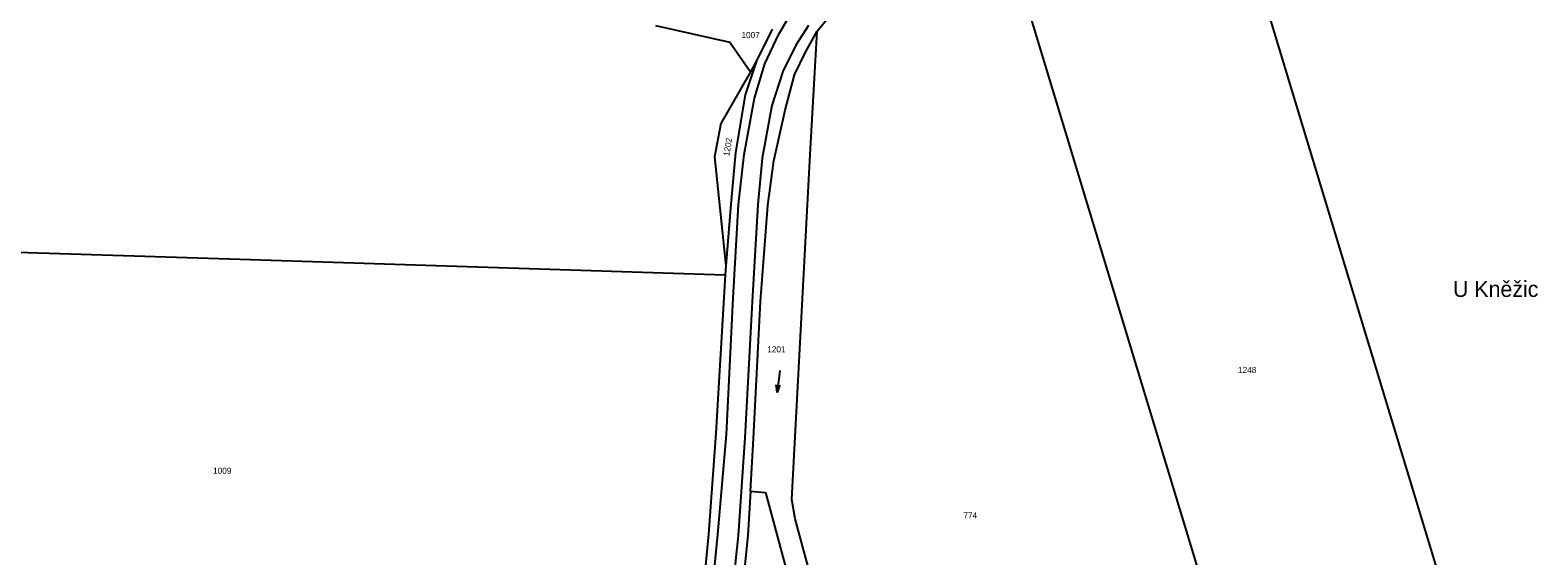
# Model space of a CAD drawing. Extents: x -812394 to -807601, y -1013097 to -1009266.
# Drawn here: x -811185.3 to -810769.5, y -1011122.9 to -1010977.8 of the extents above; entities that cross this region are included whole.
import ezdxf

# ---------------------------------------------------------------- set-up
doc = ezdxf.new("R2010")
doc.units = 0
for name, color, linetype in [('Default', 7, 'Continuous'), ('KN_HRANICE', 7, 'Continuous'), ('KN_KULTURY', 7, 'Continuous'), ('KN_PARCELY', 7, 'Continuous'), ('KN_SLUCKY', 7, 'Continuous')]:
    doc.layers.add(name, color=color, linetype=linetype)

# ---------------------------------------------------------------- blocks, each defined once
blk = doc.blocks.new('802')
at = {"layer": 'Default'}
blk.add_line((-3, 0), (3, 0), dxfattribs=at)
blk.add_lwpolyline([(1, 0.5), (3, 0), (1, -0.5)], dxfattribs=at)

msp = doc.modelspace()

# ---------------------------------------------------------------- linework, layer by layer
at = {"layer": 'KN_HRANICE'}
for p, q in [((-810854.65, -1010937.39), (-810817.55, -1011059.91)), ((-810877.77, -1011078.41), (-810915.45, -1010954)), ((-810968.23, -1010978.09), (-810963.27, -1010971.99)), ((-811012.84, -1010976.5), (-810992.33, -1010981.12)), ((-810980.68, -1010977.48), (-810984.94, -1010986.25)), ((-810971.47, -1010983.86), (-810968.23, -1010978.09)), ((-810970.21, -1011012.14), (-810968.23, -1010978.09)), ((-810992.33, -1010981.12), (-810986.67, -1010989.28)), ((-810984.94, -1010986.25), (-810988.06, -1010995.64)), ((-810984.94, -1010986.25), (-810986.67, -1010989.28)), ((-810974.52, -1010990.17), (-810971.47, -1010983.86)), ((-810986.67, -1010989.28), (-810994.78, -1011003.54)), ((-810977.06, -1010999.91), (-810974.52, -1010990.17)), ((-810988.06, -1010995.64), (-810990.73, -1011011.55)), ((-810980.21, -1011013.87), (-810977.06, -1010999.91)), ((-810994.78, -1011003.54), (-810996.57, -1011012.76)), ((-810990.73, -1011011.55), (-810992.07, -1011025.87)), ((-810996.57, -1011012.76), (-810993.43, -1011042.83)), ((-810981.88, -1011026.19), (-810980.21, -1011013.87)), ((-810975.27, -1011107.32), (-810970.21, -1011012.14)), ((-810992.07, -1011025.87), (-810993.43, -1011042.83)), ((-810983.9, -1011052.71), (-810981.88, -1011026.19)), ((-811261.12, -1011036.76), (-811127.35, -1011041.05)), ((-811127.35, -1011041.05), (-810993.58, -1011045.33)), ((-810993.43, -1011042.83), (-810993.58, -1011045.33)), ((-810993.58, -1011045.33), (-810996.23, -1011089.07)), ((-810985.77, -1011090.52), (-810983.9, -1011052.71)), ((-810817.55, -1011059.91), (-810780.44, -1011182.42)), ((-810840.09, -1011202.83), (-810877.77, -1011078.41)), ((-810996.23, -1011089.07), (-810998.22, -1011116.9)), ((-810986.65, -1011105.04), (-810985.77, -1011090.52)), ((-810986.65, -1011105.04), (-810982.45, -1011105.41)), ((-810982.45, -1011105.41), (-810956.76, -1011200.71)), ((-810974.27, -1011112.67), (-810975.27, -1011107.32)), ((-810957.61, -1011174.47), (-810974.27, -1011112.67)), ((-810998.22, -1011116.9), (-811000.96, -1011145.71))]:
    msp.add_line(p, q, dxfattribs=at)
msp.add_lwpolyline([(-810986.65, -1011105.04), (-810987.39, -1011117.32), (-810992.21, -1011165.1)], dxfattribs=at)
at = {"layer": 'KN_SLUCKY'}
for points in [[(-811000.33, -1011164.87), (-810995.6, -1011117.04), (-810993.22, -1011089.39), (-810991.44, -1011051.79), (-810989.93, -1011025.95), (-810988.35, -1011012.09), (-810985.51, -1010996.59), (-810982.68, -1010987.06), (-810978.95, -1010979.06), (-810975.35, -1010972.95)], [(-810970.63, -1010976.53), (-810974.13, -1010981.9), (-810977.67, -1010989.22), (-810980.74, -1010998.6), (-810983.37, -1011013.1), (-810984.59, -1011025.93), (-810986.15, -1011052.66), (-810988.17, -1011090.35), (-810990.05, -1011117.32), (-810995.05, -1011165.02)]]:
    msp.add_lwpolyline(points, dxfattribs=at)

# ---------------------------------------------------------------- block references
at = {"layer": 'KN_KULTURY', "rotation": -97.12696399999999}
msp.add_blockref('802', (-810978.9, -1011074.76), dxfattribs=at)

# ---------------------------------------------------------------- texts
at = {"layer": 'KN_PARCELY'}
for s, height, p in [('1007', 1.7, (-810989.13, -1010979.99)), ('U Kněžic', 4.4, (-810792.86, -1011051.44)), ('1201', 1.7, (-810982.02, -1011066.75)), ('1248', 1.7, (-810852.17, -1011072.44)), ('1009', 1.7, (-811134.86, -1011100.26)), ('774', 1.7, (-810927.91, -1011112.59))]:
    msp.add_text(s, height=height, dxfattribs=at).set_placement(p)
msp.add_text('1202', height=1.7, rotation=80.501, dxfattribs=at).set_placement((-810992.5, -1011012.67))

doc.saveas('drawing.dxf')
